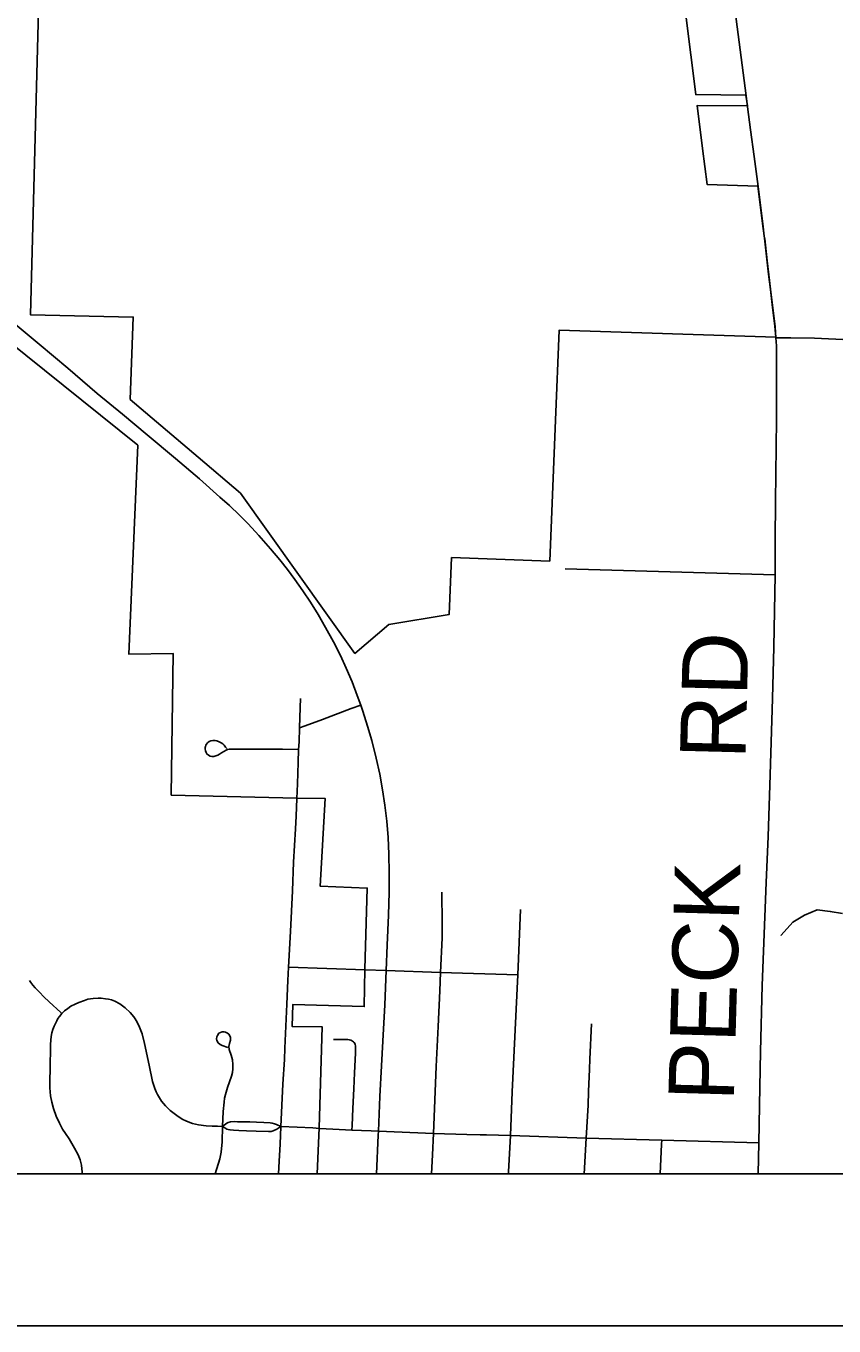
# Model space of a CAD drawing. Extents: x 0 to 34, y 0 to 22.
# Drawn here: x 26.224 to 26.924, y 9.775 to 10.902 of the extents above; entities that cross this region are included whole.
import ezdxf

# ---------------------------------------------------------------- set-up
doc = ezdxf.new("R2010")
doc.units = 0
for name, color, linetype in [('GM_X_City_Street', 7, 'Continuous'), ('GM_X_Corporation', 7, 'Continuous'), ('GM_X_County_Road', 7, 'Continuous'), ('GM_X_County_Road_Text', 7, 'Continuous'), ('GM_X_Minor_River', 7, 'Continuous'), ('GM_X_State_Route', 7, 'Continuous'), ('GM_X_Township_Road', 7, 'Continuous'), ('SH_Data', 7, 'Continuous')]:
    doc.layers.add(name, color=color, linetype=linetype)

msp = doc.modelspace()

# ---------------------------------------------------------------- linework, layer by layer
at = {"layer": 'GM_X_City_Street'}
for points in [[(26.2551, 10.0456), (26.254, 10.0467), (26.244, 10.0559), (26.2394, 10.0601), (26.2355, 10.0641), (26.2319, 10.0681), (26.2299, 10.0704), (26.2281, 10.0726), (26.227, 10.0744)], [(26.2727, 9.9067), (26.2727, 9.9081), (26.272, 9.9142), (26.2709, 9.9189), (26.2691, 9.9233), (26.2661, 9.9291), (26.2612, 9.937), (26.2582, 9.9418), (26.2557, 9.9456), (26.253, 9.9507), (26.25, 9.9568), (26.2477, 9.9633), (26.2462, 9.9688), (26.2452, 9.9744), (26.2446, 9.9812), (26.2446, 9.9893), (26.2448, 9.9961), (26.2449, 9.9998), (26.245, 10.0034), (26.2451, 10.0126), (26.2453, 10.0193), (26.2458, 10.0257), (26.2464, 10.0289), (26.2473, 10.0318), (26.2484, 10.0348), (26.2495, 10.037), (26.2507, 10.0394), (26.2516, 10.0413), (26.2529, 10.0431), (26.2551, 10.0456), (26.2574, 10.0481), (26.2603, 10.0502), (26.2629, 10.052), (26.2666, 10.0539), (26.2696, 10.0554), (26.2745, 10.0571), (26.2776, 10.0581), (26.2821, 10.0587), (26.2864, 10.0589), (26.2892, 10.0589), (26.2928, 10.0586), (26.2953, 10.0582), (26.2979, 10.0575), (26.3009, 10.0565), (26.3054, 10.054), (26.3099, 10.0506), (26.3141, 10.0467), (26.3173, 10.0428), (26.3185, 10.0412), (26.3204, 10.0382), (26.3223, 10.034), (26.3245, 10.0282), (26.3266, 10.0197), (26.3307, 10.0009), (26.3337, 9.9867), (26.3357, 9.9808), (26.3367, 9.9779), (26.338, 9.9755), (26.3415, 9.9698), (26.345, 9.9656), (26.349, 9.9618), (26.3547, 9.9572), (26.3593, 9.9541), (26.3631, 9.9523), (26.3682, 9.9503), (26.3735, 9.9492), (26.3802, 9.9484), (26.3853, 9.9481), (26.39, 9.948), (26.3944, 9.9478)], [(26.388, 9.9067), (26.392, 9.9199), (26.393, 9.9254), (26.394, 9.9345), (26.3944, 9.9478), (26.3948, 9.9607), (26.3956, 9.9688), (26.3961, 9.9724), (26.3969, 9.9756), (26.3987, 9.9816), (26.4021, 9.9913), (26.4029, 9.9946), (26.4033, 9.9978), (26.4033, 10.0014), (26.4029, 10.0056), (26.4017, 10.0097), (26.4, 10.0144), (26.3999, 10.0172), (26.4004, 10.0198), (26.4012, 10.0227), (26.4012, 10.0249), (26.4007, 10.0264), (26.3998, 10.0277), (26.3985, 10.0286), (26.3968, 10.0296), (26.3956, 10.0298), (26.3941, 10.0298), (26.3925, 10.0294), (26.3912, 10.0286), (26.3899, 10.0268), (26.3893, 10.0254), (26.3892, 10.0238), (26.3895, 10.0222), (26.3905, 10.0203), (26.3922, 10.0188), (26.3941, 10.0179), (26.399, 10.0164)], [(26.3944, 9.9478), (26.397, 9.9499), (26.398, 9.9507), (26.3992, 9.9513), (26.4013, 9.9518), (26.4044, 9.952), (26.4073, 9.9519), (26.4179, 9.9518), (26.4238, 9.9516), (26.4301, 9.9513), (26.4356, 9.9509), (26.4373, 9.9507), (26.4394, 9.9502), (26.4412, 9.9496), (26.4448, 9.9479)], [(26.3944, 9.9478), (26.3963, 9.9466), (26.3979, 9.9456), (26.3992, 9.9451), (26.4008, 9.9448), (26.4038, 9.9445), (26.4083, 9.9443), (26.4152, 9.9439), (26.4235, 9.9437), (26.4342, 9.9434), (26.4364, 9.9436), (26.4383, 9.9441), (26.4413, 9.9456), (26.4448, 9.9479)]]:
    msp.add_lwpolyline(points, dxfattribs=at)
at = {"layer": 'GM_X_Corporation'}
for points in [[(23.0715, 12.7151), (23.0715, 9.9067), (27.93, 9.9067)], [(26.2347, 10.9151), (26.2277, 10.6514), (26.3169, 10.6494), (26.3169, 10.6494), (26.3141, 10.578), (26.3731, 10.5279), (26.4098, 10.4968), (26.5091, 10.3579), (26.5386, 10.383), (26.5909, 10.3917), (26.5929, 10.4409), (26.678, 10.4379), (26.683, 10.5601), (26.6862, 10.6382), (26.8739, 10.632), (26.8731, 10.6414), (26.8709, 10.6602), (26.8693, 10.6733), (26.8677, 10.6865), (26.8641, 10.7178), (26.8628, 10.7281), (26.8584, 10.763), (26.8144, 10.7644), (26.8104, 10.7954), (26.8057, 10.8328), (26.8493, 10.8324), (26.848, 10.8418), (26.8045, 10.8423), (26.7915, 10.9458)], [(24.2537, 9.9067), (26.4763, 9.9067), (26.4782, 9.9467), (26.4806, 10.0343), (26.4547, 10.0344), (26.4552, 10.0535), (26.5172, 10.0517), (26.5177, 10.0842), (26.5198, 10.1545), (26.479, 10.1561), (26.4833, 10.232), (26.4586, 10.2325), (26.3499, 10.2351), (26.3516, 10.3577), (26.3132, 10.3572), (26.321, 10.5383), (26.047, 10.7582)]]:
    msp.add_lwpolyline(points, dxfattribs=at)
at = {"layer": 'GM_X_County_Road'}
for p, q in [((26.8495, 10.8318), (26.8482, 10.8413)), ((26.8586, 9.9067), (26.8591, 9.9337))]:
    msp.add_line(p, q, dxfattribs=at)
for points in [[(26.8482, 10.8413), (26.8297, 10.9834), (26.8225, 11.0379), (26.813, 11.1095)], [(26.8586, 10.7625), (26.8552, 10.7885), (26.8521, 10.8118), (26.8495, 10.8318)], [(26.8741, 10.6315), (26.8733, 10.6409), (26.8711, 10.6596), (26.8694, 10.6736), (26.8679, 10.6859), (26.8665, 10.6982), (26.8643, 10.7172), (26.864, 10.7196), (26.863, 10.7276), (26.8586, 10.7625)], [(26.8733, 10.4261), (26.8734, 10.4563), (26.8738, 10.4895), (26.8746, 10.5606), (26.8746, 10.6215), (26.8745, 10.6246), (26.8744, 10.628), (26.8741, 10.6315)], [(26.8741, 10.6315), (26.879, 10.6315), (26.8869, 10.6315), (26.9075, 10.631), (26.938, 10.6298)], [(26.8591, 9.9337), (26.86, 9.9819), (26.8607, 10.0128), (26.862, 10.07), (26.8656, 10.1593), (26.8672, 10.1991), (26.8692, 10.2525), (26.8712, 10.3187), (26.8721, 10.3633), (26.8733, 10.4261)]]:
    msp.add_lwpolyline(points, dxfattribs=at)
at = {"layer": 'GM_X_Minor_River'}
msp.add_lwpolyline([(26.9317, 10.1325), (26.9211, 10.1343), (26.9097, 10.1356), (26.8988, 10.131), (26.8886, 10.1248), (26.8785, 10.1136), (26.8782, 10.114)], dxfattribs=at)
at = {"layer": 'GM_X_State_Route'}
for points in [[(26.2129, 10.6448), (26.2354, 10.626), (26.2601, 10.6051), (26.2856, 10.5833), (26.3076, 10.5652), (26.329, 10.5473), (26.3534, 10.5269), (26.3744, 10.5091), (26.3921, 10.4934), (26.4002, 10.486), (26.4089, 10.4777), (26.4165, 10.4703), (26.4258, 10.4602), (26.436, 10.4485), (26.444, 10.4389), (26.4505, 10.4305), (26.457, 10.422), (26.464, 10.4121), (26.4705, 10.4023), (26.4772, 10.3915), (26.4837, 10.3802), (26.4905, 10.3678), (26.4965, 10.3561), (26.5016, 10.3451), (26.5066, 10.3333), (26.5111, 10.3214), (26.5141, 10.3131)], [(26.5141, 10.3131), (26.5159, 10.3079), (26.5201, 10.2949), (26.5238, 10.2823), (26.5276, 10.2672), (26.5306, 10.2532), (26.5331, 10.2397), (26.5351, 10.2262), (26.5367, 10.2126), (26.5379, 10.1983), (26.5386, 10.184), (26.5389, 10.1678), (26.5388, 10.151), (26.5382, 10.1311), (26.537, 10.105), (26.5362, 10.083)], [(26.5362, 10.083), (26.5349, 10.0534), (26.5333, 10.0217), (26.532, 10.0005), (26.5307, 9.9738), (26.5294, 9.9437)], [(26.5294, 9.9437), (26.5292, 9.9404), (26.5278, 9.9067)]]:
    msp.add_lwpolyline(points, dxfattribs=at)
at = {"layer": 'GM_X_Township_Road'}
for p, q in [((26.6912, 10.4312), (26.8733, 10.4261)), ((26.6502, 10.0792), (26.6527, 10.1359)), ((26.4516, 10.0858), (26.5179, 10.0836)), ((26.5179, 10.0836), (26.5362, 10.083)), ((26.5362, 10.083), (26.5834, 10.0814)), ((26.5834, 10.0814), (26.6502, 10.0792)), ((26.5294, 9.9437), (26.5771, 9.9418)), ((26.6439, 9.9399), (26.7096, 9.9378)), ((26.7079, 9.9067), (26.7096, 9.9378)), ((26.7096, 9.9378), (26.7751, 9.936)), ((26.7751, 9.936), (26.8591, 9.9337))]:
    msp.add_line(p, q, dxfattribs=at)
for points in [[(26.4611, 10.2933), (26.4617, 10.311), (26.4619, 10.3189)], [(26.4611, 10.2933), (26.4658, 10.2951), (26.4809, 10.3007), (26.5058, 10.31), (26.5141, 10.3131)], [(26.4603, 10.2746), (26.4606, 10.2813), (26.4611, 10.2933)], [(26.398, 10.2754), (26.397, 10.2767), (26.3957, 10.2783), (26.3945, 10.2795), (26.3932, 10.2803), (26.3913, 10.2813), (26.3895, 10.282), (26.3878, 10.2823), (26.386, 10.2824), (26.3843, 10.2822), (26.3828, 10.2816), (26.3814, 10.2805), (26.3804, 10.2793), (26.3798, 10.2783), (26.3795, 10.2772), (26.3793, 10.2762), (26.3793, 10.2751), (26.3795, 10.2734), (26.38, 10.2721), (26.3808, 10.2708), (26.3821, 10.2696), (26.3837, 10.2687), (26.3852, 10.2684), (26.3868, 10.2685), (26.3886, 10.269), (26.3902, 10.2697), (26.3916, 10.2705), (26.3935, 10.2716), (26.3974, 10.2741), (26.3986, 10.2745), (26.4001, 10.2749), (26.4015, 10.275), (26.4031, 10.275), (26.4142, 10.2748), (26.4261, 10.2749), (26.4462, 10.2748), (26.4603, 10.2746)], [(26.4588, 10.232), (26.4592, 10.2449), (26.4599, 10.2634), (26.4603, 10.2746)], [(26.4516, 10.0858), (26.4531, 10.1167), (26.455, 10.1521), (26.4559, 10.177), (26.4575, 10.2057), (26.458, 10.2168), (26.4588, 10.232)], [(26.5847, 10.1225), (26.5847, 10.1274), (26.5846, 10.135), (26.5845, 10.1396), (26.5843, 10.1498), (26.5843, 10.151)], [(26.5834, 10.0814), (26.5846, 10.1114), (26.5847, 10.1205), (26.5847, 10.1225)], [(26.4448, 9.9479), (26.4467, 9.9846), (26.4479, 10.0059), (26.4484, 10.0158), (26.4501, 10.0537), (26.451, 10.0744), (26.4516, 10.0858)], [(26.5771, 9.9418), (26.5796, 9.9997), (26.5812, 10.0344), (26.5826, 10.0655), (26.5834, 10.0814)], [(26.6439, 9.9399), (26.6455, 9.9777), (26.6502, 10.0792)], [(26.7096, 9.9378), (26.7112, 9.9663), (26.7117, 9.9782), (26.7124, 9.9974), (26.7128, 10.0062), (26.7143, 10.0368)], [(26.5065, 9.9446), (26.5067, 9.9487), (26.5073, 9.9633), (26.5081, 9.9805), (26.5087, 9.9942), (26.5095, 10.0113), (26.5096, 10.0157), (26.5096, 10.0169), (26.5096, 10.0178), (26.5092, 10.0188), (26.5089, 10.0197), (26.5083, 10.0205), (26.5078, 10.0211), (26.507, 10.0218), (26.5061, 10.0224), (26.5054, 10.0227), (26.5042, 10.023), (26.5029, 10.0231), (26.502, 10.0232), (26.4905, 10.0233)], [(26.4429, 9.9067), (26.4435, 9.9176), (26.4442, 9.9325), (26.4448, 9.9479)], [(26.4448, 9.9479), (26.4589, 9.9471), (26.4726, 9.9465), (26.4784, 9.9462)], [(26.4784, 9.9462), (26.4898, 9.9455), (26.5065, 9.9446)], [(26.5065, 9.9446), (26.5231, 9.944), (26.5294, 9.9437)], [(26.5756, 9.9067), (26.5763, 9.9232), (26.5771, 9.9418)], [(26.5771, 9.9418), (26.606, 9.941), (26.6177, 9.9407), (26.6232, 9.9405), (26.6439, 9.9399)], [(26.6421, 9.9067), (26.6422, 9.9085), (26.6439, 9.9399)], [(26.7738, 9.9067), (26.775, 9.9325), (26.7751, 9.936)]]:
    msp.add_lwpolyline(points, dxfattribs=at)
at = {"layer": 'SH_Data'}
msp.add_line((22.9992, 9.7749), (29.9992, 9.7749), dxfattribs=at)

# ---------------------------------------------------------------- texts
at = {"layer": 'GM_X_County_Road_Text'}
for s, rotation, p in [('RD', 88.541, (26.8476, 10.2658)), ('PECK', 88.3862, (26.8375, 9.9693))]:
    msp.add_text(s, height=0.05682, rotation=rotation, dxfattribs=at).set_placement(p)

doc.saveas('drawing.dxf')
